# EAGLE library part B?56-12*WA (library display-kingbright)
14.22mm (0.56INCH) THREE DIGIT NUMERIC DISPLAY Source: http://www.kingbright.com .. BA56-11EWA(Ver1189474895.pdf
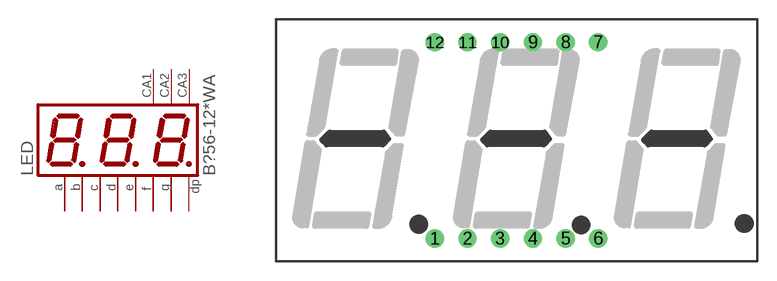
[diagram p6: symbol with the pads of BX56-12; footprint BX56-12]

Designator prefix LED

## BA56-12EWA (OC_FARNELL: unknown; OC_NEWARK: unknown), BA56-12GWA (OC_FARNELL: unknown; OC_NEWARK: unknown), BA56-12SRWA (OC_FARNELL: unknown; OC_NEWARK: unknown), BA56-12YWA (OC_FARNELL: unknown; OC_NEWARK: unknown)  [BX56-12]
1  E  pas
2  D  pas
3  DP  pas
4  C  pas
5  G  pas
7  B  pas
8  CA  pas
9  CA  pas
10  F  pas
11  A  pas
12  CA  pas

## BC56-12EWA (OC_FARNELL: unknown; OC_NEWARK: unknown), BC56-12GWA (OC_FARNELL: unknown; OC_NEWARK: unknown), BC56-12SRWA (OC_FARNELL: unknown; OC_NEWARK: unknown), BC56-12YWA (OC_FARNELL: unknown; OC_NEWARK: unknown)  [BX56-12]
Pads as for BX56-12

## Footprint BX56-12 (pad centres in mm)
14.22mm (0.56INCH) THREE DIGIT NUMERIC DISPLAY Source: http://www.kingbright.com .. BA56-11EWA(Ver1189474895.pdf
drill 0.8 pad 1.422 round: 1 -6.35,-7.62; 2 -3.81,-7.62; 3 -1.27,-7.62; 4 1.27,-7.62; 5 3.81,-7.62; 6 6.35,-7.62; 7 6.35,7.62; 8 3.81,7.62; 9 1.27,7.62; 10 -1.27,7.62; 11 -3.81,7.62; 12 -6.35,7.62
